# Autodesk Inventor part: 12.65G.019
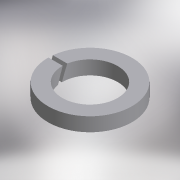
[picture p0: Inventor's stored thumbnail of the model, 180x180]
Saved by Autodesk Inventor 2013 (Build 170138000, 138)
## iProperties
Shininess: 25.0
Length Units: 11269
Angle Units: 11279
Time Units: 11290
Mass Units: 11283
Length Display Precision: 3
Angle Display Precision: 2
Created: 2001-04
Material: Steel, Mild
Description: Шайба 12.65Г.019 ГОСТ 6402-70
Document SubType Name: Modeling
Designer: tevgeniy
Mass: 3.40115 g
Surface Area: 5.87487 cm^2
Volume: 0.432716 cm^3
Density: 7.86 g/cm^3
Density: 0.0
Volumn: 0.0
Area: 0.0
PropertySet Name: Model Information
Control State: 0
Master: False
Checked Out: True
Last Check In Date: 2008-10-15
Checked Out Date: 2008-10-15
Author: tevgeniy
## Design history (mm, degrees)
node "ExtrusionBlind1" dims "d2" = 3, "d3" = 0
  sketch "Sketch1"
    geometry: C1 r 9.1 at (-266.435, -313.047)
    constraints: 1 centre point, 1 other
    dimensions: "d1" = 18.2 diameter of C1
node "Hole1" dims "d5" = 12, "d6" = 4, "d7" = 2, "d8" = 60 deg, "d9" = 8, "d10" = 118 deg
  sketch "Sketch2"
    geometry: C1 r 9.1 at (0, 0) reference
node "WorkAxis1"
workplane "Work Plane1"
workplane "Work Plane2"
node "WorkPlane1"
node "ExtrusionToFace1" dims "d18" = 0.13, "d19" = 0
  sketch "Sketch3"
    geometry: L1 (-25.913, -0.092)-(-25.913, -1); L2 (-22.913, 1)-(-25.913, -0.092); L3 (-22.913, 0.092)-(-22.913, 1); L4 (-25.913, -1)-(-22.913, 0.092); L5 (-11.456, 0)-(-37.369, 0); C1 r 9.1 at (-22.913, 0); C2 r 9.1 at (-25.913, 0)
    constraints: 10 end point, 2 centre point, 2 parallel, 1 vertical
    dimensions: "d13" = 0 horizontal distance of L2.start C1.centre; "d15" = 0 horizontal distance of L1.start C2.centre; "d17" = 160 deg angle of L4 L5
body "Solid1"
other parameters: "d0" = 18.2 (derived), "d4" = 0, "d11" = 0, "d12" = 0 (derived), "d14" = 0 (derived), "d16" = 160 deg (derived)
